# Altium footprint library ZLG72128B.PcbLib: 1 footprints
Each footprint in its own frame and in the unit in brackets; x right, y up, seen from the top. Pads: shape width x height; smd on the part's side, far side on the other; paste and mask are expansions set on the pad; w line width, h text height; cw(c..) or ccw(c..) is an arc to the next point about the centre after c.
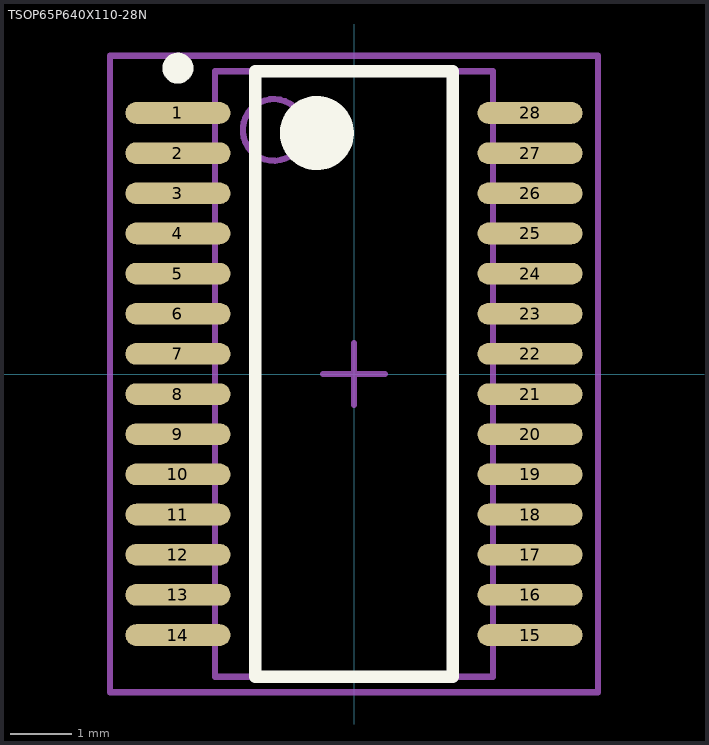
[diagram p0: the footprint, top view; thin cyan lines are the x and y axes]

## TSOP65P640X110-28N [mm] "TSOP, 28-Leads, Body 9.8x4.5mm (max), Pitch 0.65mm, IPC Medium Density"
height 1.1
pads (28):
  oval 1.7x0.35 smd: 1(-2.85,4.225) 2(-2.85,3.575) 3(-2.85,2.925) 4(-2.85,2.275) 5(-2.85,1.625) 6(-2.85,0.975) 7(-2.85,0.325) 8(-2.85,-0.325) 9(-2.85,-0.975) 10(-2.85,-1.625) 11(-2.85,-2.275) 12(-2.85,-2.925) 13(-2.85,-3.575) 14(-2.85,-4.225) 15(2.85,-4.225) 16(2.85,-3.575) 17(2.85,-2.925) 18(2.85,-2.275) 19(2.85,-1.625) 20(2.85,-0.975) 21(2.85,-0.325) 22(2.85,0.325) 23(2.85,0.975) 24(2.85,1.625) 25(2.85,2.275) 26(2.85,2.925) 27(2.85,3.575) 28(2.85,4.225)
Top Overlay:
  circle w0.6: c-0.6,3.9 r0.3
  circle w0.25: c-2.85,4.95 r0.125
  lines w0.2: -1.6,-4.9 1.6,-4.9 1.6,4.9 -1.6,4.9 -1.6,-4.9
Mechanical 13:
  circle w0.1: c-1.3,3.95 r0.5
  lines w0.1: -2.25,-4.9 2.25,-4.9 2.25,4.9 -2.25,4.9 -2.25,-4.9
Mechanical 15:
  lines w0.1: -0.5,0 0.5,0 ; 0,-0.5 0,0.5 ; -3.95,-5.15 3.95,-5.15 3.95,5.15 -3.95,5.15 -3.95,-5.15
3D body: height 1.1, standoff 0.05, extent -2.25,-4.9 2.25,4.9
